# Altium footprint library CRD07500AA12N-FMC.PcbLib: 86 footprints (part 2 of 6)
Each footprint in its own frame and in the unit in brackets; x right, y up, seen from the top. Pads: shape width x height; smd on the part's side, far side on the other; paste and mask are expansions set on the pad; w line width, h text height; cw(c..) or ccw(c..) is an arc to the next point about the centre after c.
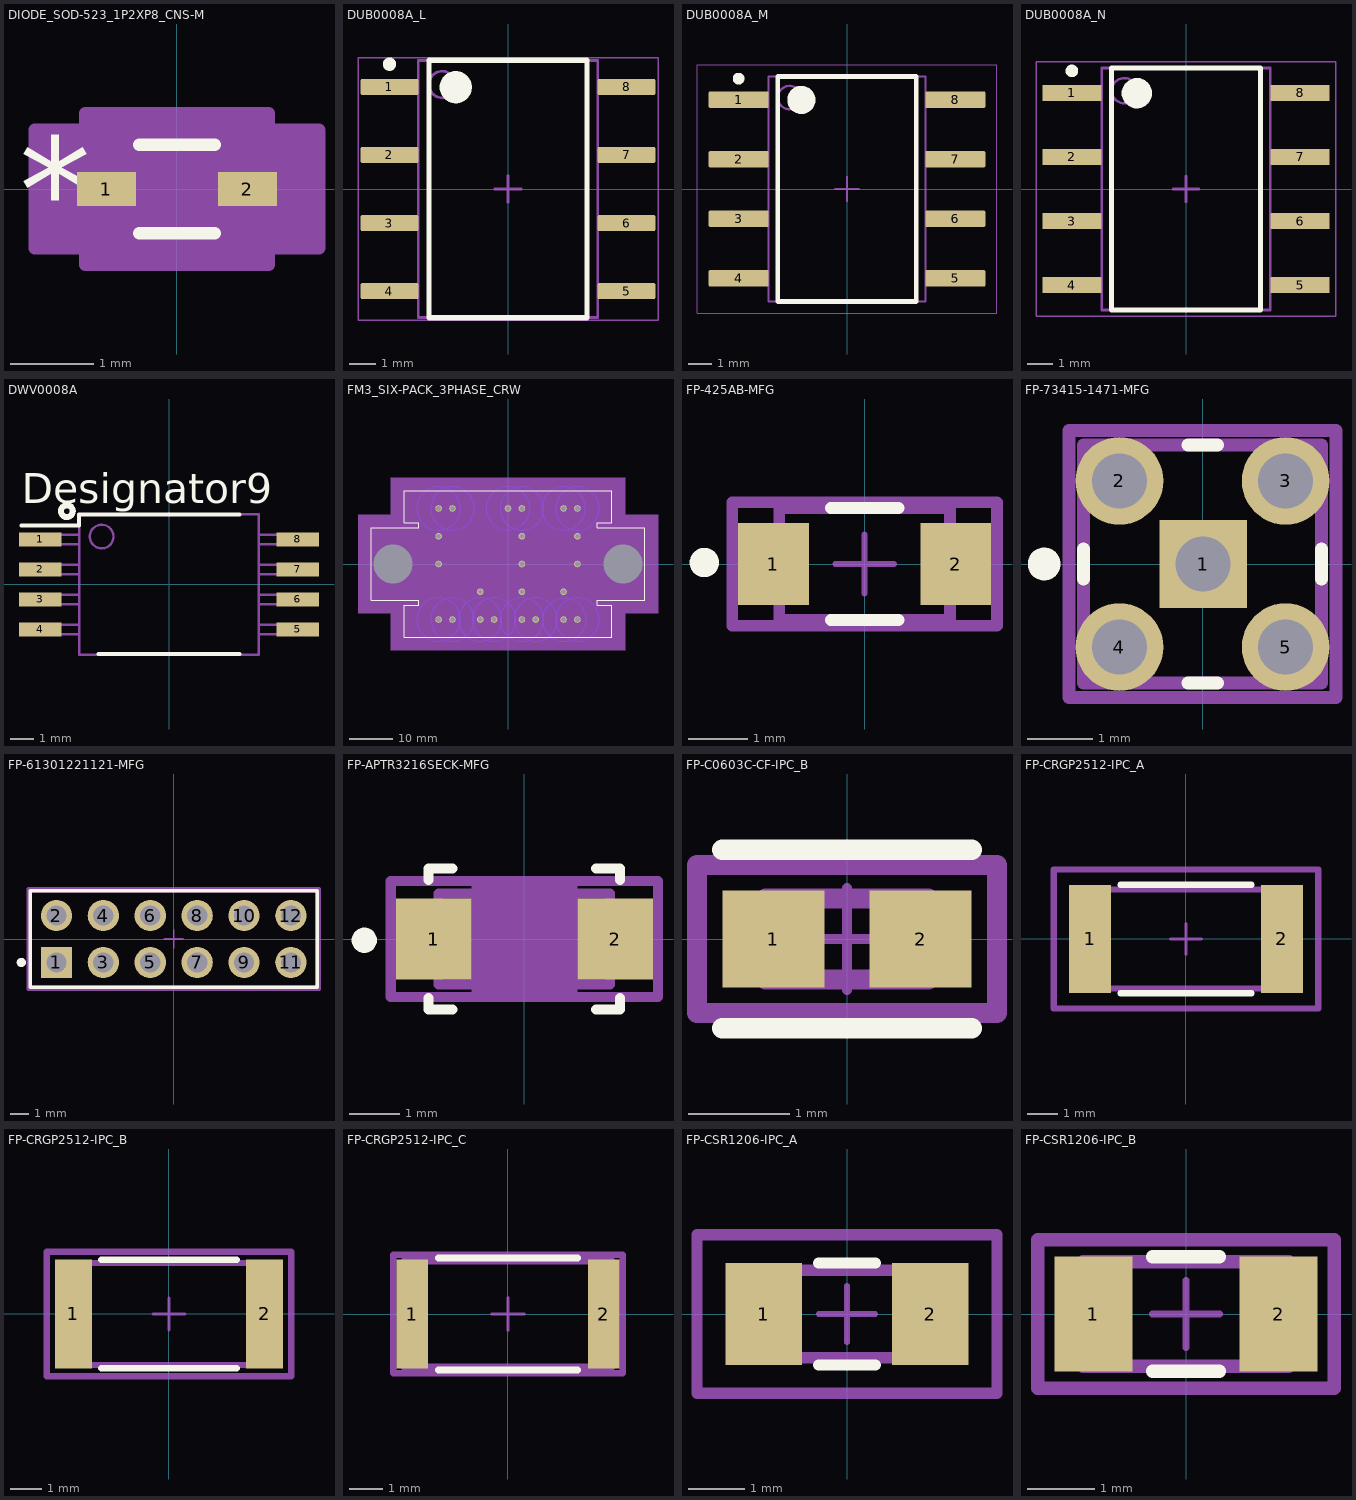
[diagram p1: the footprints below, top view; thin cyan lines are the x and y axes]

## DIODE_SOD-523_1P2XP8_CNS-M [mil]
pads (2):
  rect 28x16 smd paste+0 mask+0: 1(-33.5,0) 2(33.5,0)
Top Overlay:
  lines w6: -17.88,-21 17.88,-21 ; -17.88,21 17.88,21
  text "*" at -75,-25 h50
Mechanical 5:
  region: 55,-23.5 -55,-23.5 -55,23.5 55,23.5
Mechanical 13:
  lines w1: -23.5,-8 -15.5,-16 ; -23.5,8 -15.5,16 ; -35.5,-7 -23.5,-7 -23.5,7 -35.5,7 -35.5,-7 ; -23.5,-16 -23.5,16 23.5,16 23.5,-16 -23.5,-16 ; 23.5,-7 35.5,-7 35.5,7 23.5,7 23.5,-7
  text "*" at -26,-25 h50
Mechanical 15:
  region: -43.5,-28 -67.5,-28 -67.5,28 -43.5,28 -43.5,36 43.5,36 43.5,28 67.5,28 67.5,-28 43.5,-28 43.5,-36 -43.5,-36
  lines w6: -67.5,-28 -43.5,-28 -43.5,-36 43.5,-36 43.5,-28 67.5,-28 67.5,28 43.5,28 43.5,36 -43.5,36 -43.5,28 -67.5,28 -67.5,-28
3D body "DIODE_SOD-523_1P2XP8_CNS.step": height 31.26, standoff 0, extent -35.51,-15.98 35.51,15.98

## DUB0008A_L [mm] "SOP, 8-Leads, Body 6.7x9.6mm, Pitch 2.54mm, IPC High Density"
height 4.85
pads (8):
  rrect17% 2.15x0.6 smd: 1(-4.425,3.81) 2(-4.425,1.27) 3(-4.425,-1.27) 4(-4.425,-3.81) 5(4.425,-3.81) 6(4.425,-1.27) 7(4.425,1.27) 8(4.425,3.81)
Top Overlay:
  circle w0.25: c-4.425,4.66 r0.125
  circle w0.6: c-1.95,3.8 r0.3
  lines w0.2: -2.95,-4.8 -2.95,4.8 2.95,4.8 2.95,-4.8 -2.95,-4.8
Mechanical 1:
  text ".Designator" at -2.286,-0.381 h1
Mechanical 13:
  circle w0.1: c-2.45,3.9 r0.5
  lines w0.1: -3.35,-4.8 -3.35,4.8 3.35,4.8 3.35,-4.8 -3.35,-4.8
Mechanical 15:
  lines w0.05: -5.6,-4.9 -5.6,4.9 5.6,4.9 5.6,-4.9 -5.6,-4.9
  lines w0.1: -0.5,0 0.5,0 ; 0,-0.5 0,0.5
3D body "DUB0008A.stp": height 4.85, standoff 0, extent -5.242,-4.75 5.242,4.75

## DUB0008A_M [mm] "SOP, 8-Leads, Body 6.7x9.6mm, Pitch 2.54mm, IPC Low Density"
height 4.85
pads (8):
  rrect14% 2.55x0.7 smd: 1(-4.625,3.81) 2(-4.625,1.27) 3(-4.625,-1.27) 4(-4.625,-3.81) 5(4.625,-3.81) 6(4.625,-1.27) 7(4.625,1.27) 8(4.625,3.81)
Top Overlay:
  circle w0.25: c-4.625,4.71 r0.125
  circle w0.6: c-1.95,3.8 r0.3
  lines w0.2: -2.95,-4.8 -2.95,4.8 2.95,4.8 2.95,-4.8 -2.95,-4.8
Mechanical 1:
  text ".Designator" at -2.286,-0.254 h1
Mechanical 13:
  circle w0.1: c-2.45,3.9 r0.5
  lines w0.1: -3.35,-4.8 -3.35,4.8 3.35,4.8 3.35,-4.8 -3.35,-4.8
Mechanical 15:
  lines w0.05: -6.4,-5.3 -6.4,5.3 6.4,5.3 6.4,-5.3 -6.4,-5.3
  lines w0.1: -0.5,0 0.5,0 ; 0,-0.5 0,0.5
3D body "DUB0008A.stp": height 4.85, standoff 0, extent -5.242,-4.75 5.242,4.75

## DUB0008A_N [mm] "SOP, 8-Leads, Body 6.7x9.6mm, Pitch 2.54mm, IPC Medium Density"
height 4.85
pads (8):
  rrect15% 2.35x0.65 smd: 1(-4.525,3.81) 2(-4.525,1.27) 3(-4.525,-1.27) 4(-4.525,-3.81) 5(4.525,-3.81) 6(4.525,-1.27) 7(4.525,1.27) 8(4.525,3.81)
Top Overlay:
  circle w0.25: c-4.525,4.685 r0.125
  circle w0.6: c-1.95,3.8 r0.3
  lines w0.2: -2.95,-4.8 -2.95,4.8 2.95,4.8 2.95,-4.8 -2.95,-4.8
Mechanical 1:
  text ".Designator" at -2.54,-0.254 h1
Mechanical 13:
  circle w0.1: c-2.45,3.9 r0.5
  lines w0.1: -3.35,-4.8 -3.35,4.8 3.35,4.8 3.35,-4.8 -3.35,-4.8
Mechanical 15:
  lines w0.05: -5.95,-5.05 -5.95,5.05 5.95,5.05 5.95,-5.05 -5.95,-5.05
  lines w0.1: -0.5,0 0.5,0 ; 0,-0.5 0,0.5
3D body "DUB0008A.stp": height 4.85, standoff 0, extent -5.242,-4.75 5.242,4.75

## DWV0008A [mm]
pads (8):
  rect 1.8x0.6 smd paste+0 mask+0.051: 1(-5.45,1.905) 2(-5.45,0.635) 3(-5.45,-0.635) 4(-5.45,-1.905) 5(5.45,-1.905) 6(5.45,-0.635) 7(5.45,0.635) 8(5.45,1.905)
Top Overlay:
  circle w0.254: c-4.324,3.1 r0.25
  lines w0.17: -6.25,2.5 -3.8,2.5 -3.8,2.95 2.975,2.95 ; -2.975,-2.95 2.975,-2.95
  text "Designator9" at -6.223,3.429 h1.27
Mechanical 13:
  circle w0.1: c-2.85,2.025 r0.5
  lines w0.1: -3.805,-2.105 -5.8,-2.105 -5.8,-1.705 -3.805,-1.705 ; -3.805,-0.835 -5.8,-0.835 -5.8,-0.435 -3.805,-0.435 ; -3.805,0.435 -5.8,0.435 -5.8,0.835 -3.805,0.835 ; -3.805,1.705 -5.8,1.705 -5.8,2.105 -3.805,2.105 ; 3.805,-2.105 5.8,-2.105 5.8,-1.705 3.805,-1.705 ; 3.805,-0.835 5.8,-0.835 5.8,-0.435 3.805,-0.435 ; 3.805,0.435 5.8,0.435 5.8,0.835 3.805,0.835 ; 3.805,1.705 5.8,1.705 5.8,2.105 3.805,2.105 ; -3.8,-2.975 3.8,-2.975 3.8,2.975 -3.8,2.975 -3.8,-2.975
  text ".Designator" at -2.8,-1.435 h1.27
3D body "DWV0008A.stp": height 2.72, standoff 0.02, extent -5.768,-2.925 5.768,2.925

## FM3_SIX-PACK_3PHASE_CRW [mm]
pads (25):
  round 1.524 hole 1.1: DC+_1(-6.4,-6.4) DC+_2(3.2,-6.4) DC+_3(12.8,-6.4) DC-1(-16,0) DC-2(3.2,0) DC-3(16,0) G1(-12.8,-12.8) G2(-16,12.8) G3(-3.2,-12.8) G4(3.2,12.8) G5(6.4,-12.8) G6(16,12.8) NTC1(12.8,-12.8) NTC2(16,-12.8) S1(-16,-12.8) S2(-12.8,12.8) S3(-6.4,-12.8) S4(0,12.8) S5(3.2,-12.8) S6(12.8,12.8) U(-16,6.4) V(3.2,6.4) W(16,6.4)
  round 0 hole 9 unplated: MH1(-26.5,0) MH2(26.5,0)
Bottom Layer keep-out:
  circle w0.254: c-16,12.8 r5
  circle w0.254: c-12.8,12.8 r5
  circle w0.254: c0,12.8 r5
  circle w0.254: c3.2,12.8 r5
  circle w0.254: c12.8,12.8 r5
  circle w0.254: c16,12.8 r5
  circle w0.254: c16,-12.8 r5
  circle w0.254: c12.997,-12.859 r5
  circle w0.254: c6.4,-12.8 r5
  circle w0.254: c3.2,-12.8 r5
  circle w0.254: c-3.2,-12.8 r5
  circle w0.254: c-6.4,-12.8 r5
  circle w0.254: c-12.8,-12.8 r5
  circle w0.254: c-16,-12.8 r5
Top Overlay:
  lines w0.152: -31.521,-8.331 -20.625,-8.331 -20.625,-9.563 -23.927,-9.563 -23.927,-16.878 23.927,-16.878 23.927,-9.563 20.625,-9.563 20.625,-8.331 31.521,-8.331 31.521,8.331 20.625,8.331 20.625,9.563 23.927,9.563 23.927,16.878 -23.927,16.878 -23.927,9.563 -20.625,9.563 -20.625,8.331 -31.521,8.331 -31.521,-8.331
Bottom Courtyard:
  text "Default Padstyle: EX60Y60D43P0" at -9.525,-21.831 h1.27
Bottom 3D Body:
  region: 26.975,19.926 -26.975,19.926 -26.975,11.379 -34.569,11.379 -34.569,-11.379 -26.975,-11.379 -26.975,-19.926 26.975,-19.926 26.975,-11.379 34.569,-11.379 34.569,11.379 26.975,11.379
Top Designator:
  text ".Designator" at 7.618,-0.694 h1.52
Mechanical 13:
  drawing of 27 lines, arcs and shapes, not listed
Mechanical 15:
  region: 20.752,-9.436 20.752,-8.458 31.648,-8.458 31.648,8.458 20.752,8.458 20.752,9.436 24.054,9.436 24.054,17.005 -24.054,17.005 -24.054,9.436 -20.752,9.436 -20.752,8.458 -31.648,8.458 -31.648,-8.458 -20.752,-8.458 -20.752,-9.436 -24.054,-9.436 -24.054,-17.005 24.054,-17.005 24.054,-9.436
  lines w0.152: -31.648,-8.458 -20.752,-8.458 -20.752,-9.436 -24.054,-9.436 -24.054,-17.005 24.054,-17.005 24.054,-9.436 20.752,-9.436 20.752,-8.458 31.648,-8.458 31.648,8.458 20.752,8.458 20.752,9.436 24.054,9.436 24.054,17.005 -24.054,17.005 -24.054,9.436 -20.752,9.436 -20.752,8.458 -31.648,8.458 -31.648,-8.458
3D body: height 0.25, standoff 0, extent 0,0 0.254,0.254
3D body "McMaster-Carr 93070A095 - Alternative.STEP": height -7.7, standoff -16.5, extent 23,-3.5 30,3.5
3D body "McMaster-Carr 93070A095 - Alternative.STEP": height -7.7, standoff -16.5, extent -30,-3.5 -23,3.5
3D body "CCB0xxM12FM3(Six_Pack)_External_POD_20200723_Branded_Origin.STEP": height 11.98, standoff -4.42, extent -31.4,-16.9 31.4,16.9

## FP-425AB-MFG [mm]
pads (2):
  rect 1.2x1.4 smd paste+0 mask+0: 1(-1.55,0) 2(1.55,0)
Top Overlay:
  circle w0.25: c-2.725,0.025 r0.125
  lines w0.2: -0.575,-0.95 0.575,-0.95 ; -0.575,0.95 0.575,0.95
Mechanical 5:
  lines w0.2: -2.25,-1.05 2.25,-1.05 2.25,1.05 -2.25,1.05 -2.25,-1.05
  text ".Designator" at 0,0 h1
Mechanical 13:
  lines w0.2: -1.45,-0.95 1.45,-0.95 1.45,0.95 -1.45,0.95 -1.45,-0.95
Mechanical 15:
  lines w0.2: -2.25,-1.05 2.25,-1.05 2.25,1.05 -2.25,1.05 -2.25,-1.05
Mechanical 16:
  lines w0.1: -0.5,0 0.5,0 ; 0,-0.5 0,0.5
3D body "Diode_ON_Semiconductor_US1MFA_eec.STEP": height 0.25, standoff 0, extent -2.25,-1.05 2.25,1.05

## FP-73415-1471-MFG [mm]
pads (5):
  rect 1.34x1.34 hole 0.84 paste-1000 mask+0: 1(0.01,0)
  round 1.34 hole 0.84 paste-1000 mask+0: 2(-1.27,1.27) 3(1.27,1.27) 4(-1.27,-1.27) 5(1.27,-1.27)
Top Overlay:
  circle w0.25: c-2.42,0 r0.125
  lines w0.2: -1.82,-0.225 -1.82,0.225 ; -0.225,-1.82 0.225,-1.82 ; -0.225,1.82 0.225,1.82 ; 1.82,-0.225 1.82,0.225
Mechanical 5:
  lines w0.2: -2.04,-2.04 2.04,-2.04 2.04,2.04 -2.04,2.04 -2.04,-2.04
  text ".Designator" at 0,0.188 h1
Mechanical 13:
  lines w0.2: -1.82,-1.82 1.82,-1.82 1.82,1.82 -1.82,1.82 -1.82,-1.82
Mechanical 15:
  lines w0.2: -2.04,-2.04 2.04,-2.04 2.04,2.04 -2.04,2.04 -2.04,-2.04
Mechanical 16:
  lines w0.1: -0.5,0 0.5,0 ; 0,-0.5 0,0.5
3D body "Conn_Molex_73415-1471_eec.STEP": height 0.25, standoff 0, extent -2.04,-2.04 2.04,2.04

## FP-61301221121-MFG [mm]
pads (12):
  rect 1.7x1.7 hole 1.1 paste-1000 mask+0: 1(-6.35,-1.27)
  round 1.7 hole 1.1 paste-1000 mask+0: 2(-6.35,1.27) 3(-3.81,-1.27) 4(-3.81,1.27) 5(-1.27,-1.27) 6(-1.27,1.27) 7(1.27,-1.27) 8(1.27,1.27) 9(3.81,-1.27) 10(3.81,1.27) 11(6.35,-1.27) 12(6.35,1.27)
Top Overlay:
  circle w0.25: c-8.255,-1.27 r0.125
  lines w0.2: -7.77,-2.615 7.77,-2.615 7.77,2.615 -7.77,2.615 -7.77,-2.615
Mechanical 5:
  lines w0.2: -7.87,-2.715 7.87,-2.715 7.87,2.715 -7.87,2.715 -7.87,-2.715
  text ".Designator" at 0,0.188 h1
Mechanical 13:
  lines w0.2: -7.77,-2.615 7.77,-2.615 7.77,2.615 -7.77,2.615 -7.77,-2.615
Mechanical 15:
  lines w0.2: -7.87,-2.715 7.87,-2.715 7.87,2.715 -7.87,2.715 -7.87,-2.715
Mechanical 16:
  lines w0.1: -0.5,0 0.5,0 ; 0,-0.5 0,0.5
3D body "Conn_Wurth_Electronics_61301221121_eec.STEP": height 0.25, standoff 0, extent -7.87,-2.715 7.87,2.715

## FP-APTR3216SECK-MFG [mm]
pads (2):
  rect 1.5x1.6 smd paste+0 mask+0: 1(-1.8,0) 2(1.8,0)
Top Overlay:
  circle w0.25: c-3.175,-0.025 r0.125
  lines w0.2: -1.9,-1.175 -1.9,-1.4 -1.425,-1.4 ; -1.9,1.175 -1.9,1.4 -1.425,1.4 ; 1.425,-1.4 1.9,-1.4 1.9,-1.175 ; 1.425,1.4 1.9,1.4 1.9,1.175
Bottom 3D Body:
  rectangle: -1.05,-1.15 1.05,1.15
Mechanical 5:
  lines w0.2: -2.65,-1.15 2.65,-1.15 2.65,1.15 -2.65,1.15 -2.65,-1.15
  text ".Designator" at 0,0 h1
Mechanical 13:
  lines w0.2: -1.7,-0.9 1.7,-0.9 1.7,0.9 -1.7,0.9 -1.7,-0.9
Mechanical 15:
  lines w0.2: -2.65,-1.15 2.65,-1.15 2.65,1.15 -2.65,1.15 -2.65,-1.15
Mechanical 16:
  lines w0.1: -0.5,0 0.5,0 ; 0,-0.5 0,0.5
3D body "LED 1206 - PURPLE.STEP": height 1.1, standoff 0, extent -1.6,-0.8 1.6,0.802

## FP-C0603C-CF-IPC_B [mm]
pads (2):
  rect 1.007x0.958 smd paste+0 mask+0: 1(-0.726,0) 2(0.726,0)
Top Overlay:
  lines w0.2: -1.229,-0.879 1.229,-0.879 ; -1.229,0.879 1.229,0.879
Mechanical 5:
  lines w0.2: -1.479,-0.729 -1.479,0.729 1.479,0.729 1.479,-0.729 -1.479,-0.729
  text ".Designator" at 0,0.188 h1
Mechanical 13:
  lines w0.2: -0.8,-0.4 -0.8,0.4 0.8,0.4 0.8,-0.4 -0.8,-0.4
Mechanical 15:
  lines w0.2: -1.479,-0.729 -1.479,0.729 1.479,0.729 1.479,-0.729 -1.479,-0.729
Mechanical 16:
  lines w0.1: -0.5,0 0.5,0 ; 0,-0.5 0,0.5
3D body "Cap_KEMET_C0603C272M5JACTU_eec.STEP": height 0.25, standoff 0, extent -1.479,-0.729 1.479,0.729

## FP-CRGP2512-IPC_A [mm]
pads (2):
  rect 1.358x3.506 smd paste+0 mask+0: 1(-3.102,0) 2(3.102,0)
Top Overlay:
  lines w0.2: -2.123,-1.753 2.123,-1.753 ; -2.123,1.753 2.123,1.753
Mechanical 5:
  lines w0.2: -4.281,-2.253 4.281,-2.253 4.281,2.253 -4.281,2.253 -4.281,-2.253
  text ".Designator" at 0,0.188 h1
Mechanical 13:
  lines w0.2: -3.175,-1.6 3.175,-1.6 3.175,1.6 -3.175,1.6 -3.175,-1.6
Mechanical 15:
  lines w0.2: -4.281,-2.253 4.281,-2.253 4.281,2.253 -4.281,2.253 -4.281,-2.253
Mechanical 16:
  lines w0.1: -0.5,0 0.5,0 ; 0,-0.5 0,0.5
3D body "Res_TE_CRGP2512F47R_eec.STEP": height 0.25, standoff 0, extent -4.281,-2.253 4.281,2.253

## FP-CRGP2512-IPC_B [mm]
pads (2):
  rect 1.158x3.406 smd paste+0 mask+0: 1(-3.002,0) 2(3.002,0)
Top Overlay:
  lines w0.2: -2.123,-1.703 2.123,-1.703 ; -2.123,1.703 2.123,1.703
Mechanical 5:
  lines w0.2: -3.831,-1.953 3.831,-1.953 3.831,1.953 -3.831,1.953 -3.831,-1.953
  text ".Designator" at 0,0.188 h1
Mechanical 13:
  lines w0.2: -3.175,-1.6 3.175,-1.6 3.175,1.6 -3.175,1.6 -3.175,-1.6
Mechanical 15:
  lines w0.2: -3.831,-1.953 3.831,-1.953 3.831,1.953 -3.831,1.953 -3.831,-1.953
Mechanical 16:
  lines w0.1: -0.5,0 0.5,0 ; 0,-0.5 0,0.5
3D body "Res_TE_CRGP2512F47R_eec.STEP": height 0.25, standoff 0, extent -3.831,-1.953 3.831,1.953

## FP-CRGP2512-IPC_C [mm]
pads (2):
  rect 0.958x3.306 smd paste+0 mask+0: 1(-2.902,0) 2(2.902,0)
Top Overlay:
  lines w0.2: -2.123,-1.7 2.123,-1.7 ; -2.123,1.7 2.123,1.7
Mechanical 5:
  lines w0.2: -3.481,-1.8 3.481,-1.8 3.481,1.8 -3.481,1.8 -3.481,-1.8
  text ".Designator" at 0,0.188 h1
Mechanical 13:
  lines w0.2: -3.175,-1.6 3.175,-1.6 3.175,1.6 -3.175,1.6 -3.175,-1.6
Mechanical 15:
  lines w0.2: -3.481,-1.8 3.481,-1.8 3.481,1.8 -3.481,1.8 -3.481,-1.8
Mechanical 16:
  lines w0.1: -0.5,0 0.5,0 ; 0,-0.5 0,0.5
3D body "Res_TE_CRGP2512F47R_eec.STEP": height 0.25, standoff 0, extent -3.481,-1.8 3.481,1.8

## FP-CSR1206-IPC_A [mm]
pads (2):
  rect 1.356x1.808 smd paste+0 mask+0: 1(-1.476,0) 2(1.476,0)
Top Overlay:
  lines w0.2: -0.498,-0.904 0.498,-0.904 ; -0.498,0.904 0.498,0.904
Mechanical 5:
  lines w0.2: -2.654,-1.404 2.654,-1.404 2.654,1.404 -2.654,1.404 -2.654,-1.404
  text ".Designator" at 0,0.188 h1
Mechanical 13:
  lines w0.2: -1.525,-0.775 1.525,-0.775 1.525,0.775 -1.525,0.775 -1.525,-0.775
Mechanical 15:
  lines w0.2: -2.654,-1.404 2.654,-1.404 2.654,1.404 -2.654,1.404 -2.654,-1.404
Mechanical 16:
  lines w0.1: -0.5,0 0.5,0 ; 0,-0.5 0,0.5
3D body "Res_Stackpole_Electronics_CSR1206FKR500_eec.STEP": height 0.25, standoff 0, extent -2.654,-1.404 2.654,1.404

## FP-CSR1206-IPC_B [mil]
pads (2):
  rect 45.5x67.25 smd paste+0 mask+0: 1(-54.18,0) 2(54.18,0)
Top Overlay:
  lines w7.87: -19.62,-33.63 19.62,-33.63 ; -19.62,33.63 19.62,33.63
Mechanical 5:
  lines w7.87: -86.78,-43.47 86.78,-43.47 86.78,43.47 -86.78,43.47 -86.78,-43.47
  text ".Designator" at 0,7.4 h39.37
Mechanical 13:
  lines w7.87: -60.04,-30.51 60.04,-30.51 60.04,30.51 -60.04,30.51 -60.04,-30.51
Mechanical 15:
  lines w7.87: -86.78,-43.47 86.78,-43.47 86.78,43.47 -86.78,43.47 -86.78,-43.47
Mechanical 16:
  lines w3.94: -19.68,0 19.68,0 ; 0,-19.68 0,19.68
3D body "Res_Stackpole_Electronics_CSR1206FKR500_eec.STEP": height 10, standoff 0, extent -86.78,-43.47 86.78,43.47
